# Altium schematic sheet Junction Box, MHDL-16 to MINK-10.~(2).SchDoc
size Tabloid; Organization: Monterey Bay Aquarium Research Institute; Address1: 7700 Sandholdt Rd; Address2: Moss Landing, CA 95039-9644; CompanyName: MBARI
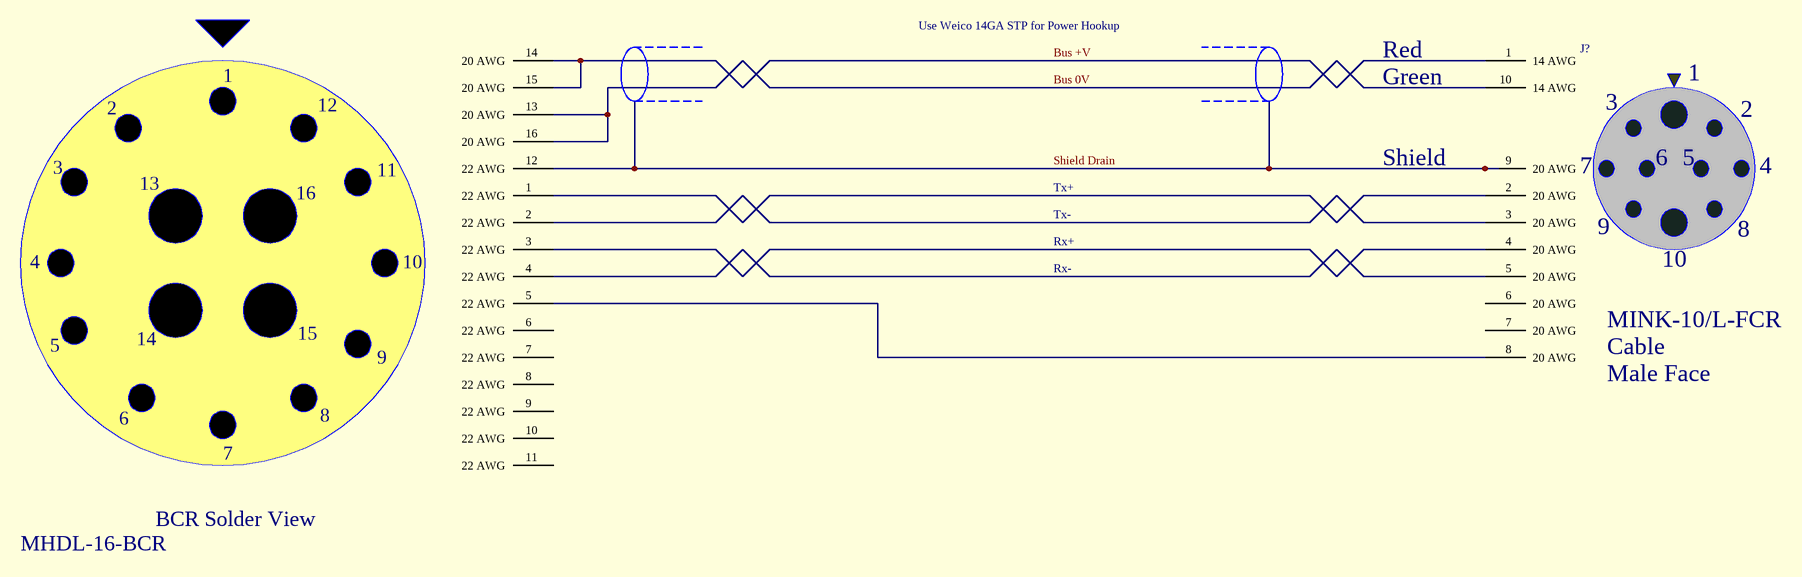
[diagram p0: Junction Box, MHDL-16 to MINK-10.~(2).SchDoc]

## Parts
(Parts that share a designator on the sheet are numbered #1, #2 ... from top to bottom, then left to right.)
J?#1  MINK-10/L-FCR  DescSheet: Cable  View: Male Face
J?#2  MHDL-16-BCR

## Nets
Bus 0V: J?#1.10(14_AWG) J?#2.13(20_AWG) J?#2.16(20_AWG)
Bus +V: J?#1.1(14_AWG) J?#2.14(20_AWG) J?#2.15(20_AWG)
Shield Drain: J?#1.9(20_AWG) J?#2.12(22_AWG)
NetJ?#1_2: J?#1.2(20_AWG) J?#2.1(22_AWG)
NetJ?#1_3: J?#1.3(20_AWG) J?#2.2(22_AWG)
NetJ?#1_4: J?#1.4(20_AWG) J?#2.3(22_AWG)
NetJ?#1_5: J?#1.5(20_AWG) J?#2.4(22_AWG)
NetJ?#1_8: J?#1.8(20_AWG) J?#2.5(22_AWG)

Not connected (* = marked no-connect by the designer): J?#1 6(20_AWG) 7(20_AWG); J?#2 6(22_AWG) 7(22_AWG) 8(22_AWG) 9(22_AWG) 10(22_AWG) 11(22_AWG)

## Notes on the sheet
- Use Weico 14GA STP for Power Hookup
- Red
- Green
- Tx+
- Shield
- Tx-
- Rx+
- Rx-

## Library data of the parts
J?#1 = SEACON-MINK-10-BCR-PINS: Seacon MINK-10/L-BCR Connector
J?#2 = MHDL-16-BCR-SOLDER: Impulse MHDL 16 FCR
